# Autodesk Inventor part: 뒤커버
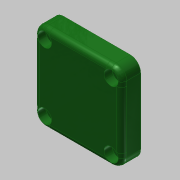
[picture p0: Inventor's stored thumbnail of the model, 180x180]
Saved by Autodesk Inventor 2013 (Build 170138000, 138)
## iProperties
Created: 2018-07
Part Number: 뒤커버
Material: 알루미늄 6061
Document SubType Name: Modeling
Designer: mduedu
Density: 1 g/cm^3
Author: mduedu
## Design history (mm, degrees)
sketch "스케치1"
  geometry: C1 r 16 at (0, 0); 1 further point
  constraints: 1 centre point, 1 coincident
  dimensions: "d0" = 32 diameter of C1
extrude "돌출1" new body sketch "스케치1" distance "d1" = 3; taper "d2" = 0 deg
sketch "스케치2"
  geometry: L1 (-25, -25)-(25, -25); L2 (25, -25)-(25, 25); L3 (25, 25)-(-25, 25); L4 (-25, 25)-(-25, -25); L5 (-25, -25)-(25, 25); L6 (25, -25)-(-25, 25); 1 further point
  constraints: 12 end point, 2 midpoint, 2 parallel, 1 horizontal, 1 perpendicular
  dimensions: "d3" = 50 distance of L3.end L2.end; "d4" = 50 distance of L2.end L1.end
extrude "돌출2" join sketch "스케치2" distance "d5" = 11; taper "d6" = 0 deg
hole "구멍1" diameter "d9" = 25; stored, may be unused: countersink angle "d13" = 90 deg, drill point angle "d15" = 0 deg; dims "d7" = 10, "d8" = 10, "d10" = 6, "d11" = 4, "d12" = 2, "d14" = 3
fillet "모깎기2" dims "d26" = 3
fillet "모깎기3" dims "d27" = 6
sketch "스케치5"
  geometry: L1 (25, -19)-(25, 19) reference; L2 (19, 25)-(-19, 25) reference; L3 (-25, 19)-(-25, -19) reference; L4 (-19, -25)-(19, -25) reference; A1 r 6 centre (19, -19) between (19, -25) and (25, -19) reference; A2 r 6 centre (19, 19) between (25, 19) and (19, 25) reference; A3 r 6 centre (-19, 19) between (-19, 25) and (-25, 19) reference; A4 r 6 centre (-19, -19) between (-25, -19) and (-19, -25) reference; 5 further points
  constraints: 4 coincident
hole "구멍2" sketch "스케치5" at (-19, 19), (19, 19), (19, -19), (-19, -19) diameter "d28" = 4.5; stored, may be unused: countersink angle "d32" = 90 deg, drill point angle "d34" = 0 deg; dims "d29" = 6, "d30" = 8, "d31" = 4.6, "d33" = 3
fillet "모깎기4" dims "d35" = 3
chamfer "모따기2" distance "d36" = 1; stored, may be unused: second distance "d37" = 2, angle "d38" = 45 deg
node "솔리드1"
node "투영된 루프1"
